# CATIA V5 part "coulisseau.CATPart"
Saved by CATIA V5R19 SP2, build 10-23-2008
Part number: coulisseau
Publications: "Esquisse.6", "hauteur du coulisseau"
Bounding box of the stored display mesh (mm): x -65 to -60, y -11.739 to -2.739, z -5 to 5
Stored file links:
  C:\Users\Thinkmotion2\Desktop\Pack 1\IAO_2010_1396_fvigouroux\vigouroux\vigouroux\coulisseau.CATPart
  C:\Users\Thinkmotion2\Desktop\Pack 1\IAO_2010_1396_fvigouroux\vigouroux\vigouroux\mecanisme IAO.CATProduct
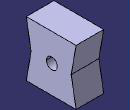
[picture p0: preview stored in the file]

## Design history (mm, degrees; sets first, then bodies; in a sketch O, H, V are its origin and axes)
Parameters
  `hauteur du coulisseau` = 5 mm
External parameters (linked from other documents)
  `External.profondeur rainure disque` = 5 mm
Set1
  Plane1: linked copy from another document
  Plane2: linked copy from another document
  Line1: linked copy from another document
  Point1: linked copy from another document
Body1 (main body)
  Sketch1 on Plane1, origin (-60, 0, 0), H (0, 1, 0), V (0, 0, 1)
    point P1 (-10.857, 0)
    line L1 (-10.857, 0) -> (-11.7386, 5)
    point P2 (-11.7386, 5)
    line L2 (-11.7386, 5) -> (-2.7386, 5)
    point P3 (-2.7386, 5)
    line L3 (-2.7386, 5) -> (-3.6202, 0)
    point P4 (-3.6202, 0)
    point P5 (-2.7386, -5)
    point P6 (-11.7386, -5)
    line L4 (-11.7386, -5) -> (-2.7386, -5)
    point P7 (-3.6202, 0)
    point P8 (-2.7386, -5)
    line L5 (-2.7386, -5) -> (-3.6202, 0)
    point P9 (-11.7386, -5)
    point P10 (-10.857, 0)
    line L6 (-10.857, 0) -> (-11.7386, -5)
    circle A1 centre (-7.1201, 0) radius 1
    point P11 (-7.1201, 0)
    reference projected point E1 (-7.1201, 0) from Point1
    angle L1 L2 = 80
    angle L3 L2 = 80
    length L2 = 9
    distance L2 H = 5 {= `hauteur du coulisseau`}
    radius A1 = 1
    distance P11 P4 = 3.4998
    distance P11 E1 = 0
    coincidence: P1 H, P4 H, P1 P10, P4 P7, P5 P8, P6 P9, P11 H
    horizontal: L2 H
    symmetry: P3 P5 H, P2 P6 H, L2 L4 H, P4 P7 H, P3 P8 H, L3 L5 H, P2 P9 H, P1 P10 H, L1 L6 H
  Pad1: profile Sketch1, direction (-1, 0, 0), length 5 {= `External.profondeur rainure disque`}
